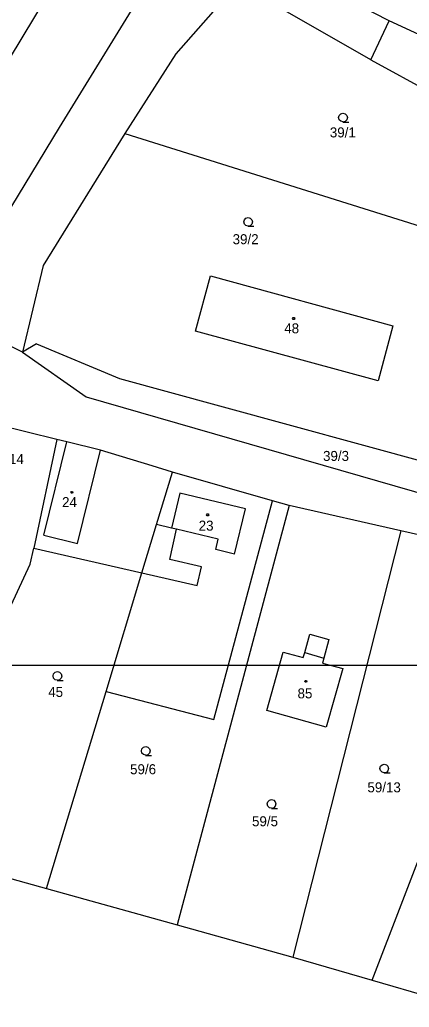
# Model space of a CAD drawing. Extents: x -752500 to -750336, y -1035826 to -1033500.
# Drawn here: x -751563.4 to -751497.1, y -1034558.1 to -1034390.2 of the extents above; entities that cross this region are included whole.
import ezdxf

# ---------------------------------------------------------------- set-up
doc = ezdxf.new("R2010")
doc.units = 0
for name, color, linetype in [('Default', 7, 'Continuous'), ('Hranice parcel', 7, 'Continuous'), ('ML1000', 7, 'Continuous'), ('Parcelní čísla', 7, 'Continuous'), ('Vnitřní kresba', 7, 'Continuous'), ('Značky budov', 7, 'Continuous'), ('Značky kultur', 7, 'Continuous')]:
    doc.layers.add(name, color=color, linetype=linetype)

# ---------------------------------------------------------------- blocks, each defined once
blk = doc.blocks.new('304')
at = {"layer": 'Default'}
blk.add_lwpolyline([(0, 0), (-0.38, 0.1), (-0.65, 0.37), (-0.75, 0.74), (-0.65, 1.11), (-0.38, 1.38), (-0.01, 1.48), (0.36, 1.38), (0.63, 1.11), (0.73, 0.73), (0.63, 0.35), (0.36, 0.08), (-0.02, -0.02), (0.98, -0.02)], dxfattribs=at)
blk = doc.blocks.new('402')
at = {"layer": 'Default'}
blk.add_lwpolyline([(0.09, 0.15), (0.18, 0), (0.09, -0.15), (-0.09, -0.15), (-0.18, 0), (-0.09, 0.15), (0.09, 0.15)], dxfattribs=at)

msp = doc.modelspace()

# ---------------------------------------------------------------- linework, layer by layer
at = {"layer": 'Hranice parcel'}
for p, q in [((-751556.65, -1034408.47), (-751528.27, -1034362.22)), ((-751526.33, -1034384.01), (-751536.85, -1034395.95)), ((-751503.65, -1034396.98), (-751526.33, -1034384.01)), ((-751536.85, -1034395.95), (-751545.55, -1034409.5)), ((-751503.65, -1034396.98), (-751492.88, -1034402.89)), ((-751569.4, -1034429.41), (-751556.65, -1034408.47)), ((-751545.55, -1034409.5), (-751559.45, -1034431.95)), ((-751545.55, -1034409.5), (-751476.6, -1034431.17)), ((-751559.45, -1034431.95), (-751563, -1034446.73)), ((-751533.53, -1034443.11), (-751530.98, -1034433.73)), ((-751530.98, -1034433.73), (-751499.9, -1034442.24)), ((-751563, -1034446.73), (-751578.94, -1034438.89)), ((-751502.42, -1034451.59), (-751533.53, -1034443.11)), ((-751499.9, -1034442.24), (-751502.42, -1034451.59)), ((-751560.58, -1034445.29), (-751563, -1034446.73)), ((-751560.58, -1034445.29), (-751546.49, -1034451.2)), ((-751563, -1034446.73), (-751552.12, -1034454.31)), ((-751546.49, -1034451.2), (-751529.41, -1034455.82)), ((-751552.12, -1034454.31), (-751487.6, -1034472.9)), ((-751557.12, -1034461.54), (-751578.63, -1034456.23)), ((-751529.41, -1034455.82), (-751486.65, -1034467.5)), ((-751557.12, -1034461.54), (-751561.07, -1034480.02)), ((-751555.41, -1034461.96), (-751557.12, -1034461.54)), ((-751549.7, -1034463.37), (-751555.41, -1034461.96)), ((-751540.9, -1034466.02), (-751549.7, -1034463.37)), ((-751537.45, -1034467.09), (-751540.9, -1034466.02)), ((-751540.14, -1034475.99), (-751537.45, -1034467.09)), ((-751520.44, -1034471.97), (-751537.45, -1034467.09)), ((-751530.39, -1034509.17), (-751520.44, -1034471.97)), ((-751517.58, -1034472.79), (-751520.44, -1034471.97)), ((-751517.58, -1034472.79), (-751536.64, -1034544.11)), ((-751498.58, -1034477.07), (-751517.58, -1034472.79)), ((-751542.64, -1034484.25), (-751540.14, -1034475.99)), ((-751498.58, -1034477.07), (-751516.94, -1034549.6)), ((-751492.7, -1034478.41), (-751498.58, -1034477.07)), ((-751561.66, -1034482.75), (-751561.07, -1034480.02)), ((-751561.07, -1034480.02), (-751542.64, -1034484.25)), ((-751566, -1034492.05), (-751561.66, -1034482.75)), ((-751548.74, -1034504.43), (-751542.64, -1034484.25)), ((-751514.93, -1034497.79), (-751514.08, -1034494.65)), ((-751514.08, -1034494.65), (-751510.82, -1034495.58)), ((-751510.82, -1034495.58), (-751511.69, -1034498.74)), ((-751521.36, -1034507.66), (-751518.61, -1034497.73)), ((-751518.61, -1034497.73), (-751515.17, -1034498.64)), ((-751515.17, -1034498.64), (-751514.93, -1034497.79)), ((-751511.69, -1034498.74), (-751511.92, -1034499.6)), ((-751511.92, -1034499.6), (-751508.44, -1034500.51)), ((-751508.44, -1034500.51), (-751511.29, -1034510.46)), ((-751558.88, -1034537.93), (-751548.74, -1034504.43)), ((-751548.74, -1034504.43), (-751530.39, -1034509.17)), ((-751503.46, -1034553.49), (-751485.13, -1034505.95)), ((-751511.29, -1034510.46), (-751521.36, -1034507.66)), ((-751572.63, -1034534.09), (-751558.88, -1034537.93)), ((-751558.88, -1034537.93), (-751536.64, -1034544.11)), ((-751536.64, -1034544.11), (-751516.94, -1034549.6)), ((-751516.94, -1034549.6), (-751503.46, -1034553.49)), ((-751503.46, -1034553.49), (-751487.48, -1034558.11))]:
    msp.add_line(p, q, dxfattribs=at)
at = {"layer": 'ML1000'}
msp.add_lwpolyline([(-751250, -1034500), (-751875, -1034500), (-752500, -1034500)], dxfattribs=at)
at = {"layer": 'Vnitřní kresba'}
for p, q in [((-751520.57, -1034323.02), (-751580.81, -1034422.5)), ((-751500.54, -1034390.33), (-751519.38, -1034380.69)), ((-751503.65, -1034396.98), (-751500.54, -1034390.33)), ((-751488.96, -1034395.74), (-751500.54, -1034390.33)), ((-751559.33, -1034477.82), (-751555.41, -1034461.96)), ((-751553.62, -1034479.23), (-751549.7, -1034463.37)), ((-751537.6, -1034476.61), (-751540.14, -1034475.99)), ((-751536.74, -1034476.82), (-751537.6, -1034476.61)), ((-751559.33, -1034477.82), (-751553.62, -1034479.23)), ((-751542.64, -1034484.25), (-751533.23, -1034486.41)), ((-751514.93, -1034497.79), (-751511.69, -1034498.74))]:
    msp.add_line(p, q, dxfattribs=at)
for points in [[(-751526.86, -1034481.05), (-751525.01, -1034473.37), (-751536.17, -1034470.68), (-751537.6, -1034476.61)], [(-751533.23, -1034486.41), (-751532.5, -1034483.19), (-751537.92, -1034481.95), (-751536.74, -1034476.82)], [(-751526.86, -1034481.05), (-751530.08, -1034480.28), (-751529.66, -1034478.53), (-751536.74, -1034476.82)]]:
    msp.add_lwpolyline(points, dxfattribs=at)

# ---------------------------------------------------------------- block references
at = {"layer": 'Značky budov'}
for p in [(-751516.81, -1034440.97), (-751554.56, -1034470.55), (-751531.46, -1034474.37), (-751514.74, -1034502.69)]:
    msp.add_blockref('402', p, dxfattribs=at)
at = {"layer": 'Značky kultur'}
for p in [(-751508.4, -1034407.54), (-751524.55, -1034425.28), (-751557.03, -1034502.51), (-751541.99, -1034515.25), (-751501.38, -1034518.24), (-751520.56, -1034524.27)]:
    msp.add_blockref('304', p, dxfattribs=at)

# ---------------------------------------------------------------- texts
at = {"layer": 'Parcelní čísla'}
for s, p in [('39/1', (-751510.65, -1034410.18)), ('39/2', (-751527.2, -1034428.34)), ('48', (-751518.41, -1034443.5)), ('39/3', (-751511.81, -1034465.2)), ('59/14', (-751568.43, -1034465.73)), ('24', (-751556.24, -1034473.06)), ('23', (-751532.98, -1034477.05)), ('45', (-751558.6, -1034505.34)), ('85', (-751516.15, -1034505.58)), ('59/6', (-751544.66, -1034518.48)), ('59/13', (-751504.25, -1034521.56)), ('59/5', (-751523.9, -1034527.33))]:
    msp.add_text(s, height=1.7, dxfattribs=at).set_placement(p)

doc.saveas('drawing.dxf')
